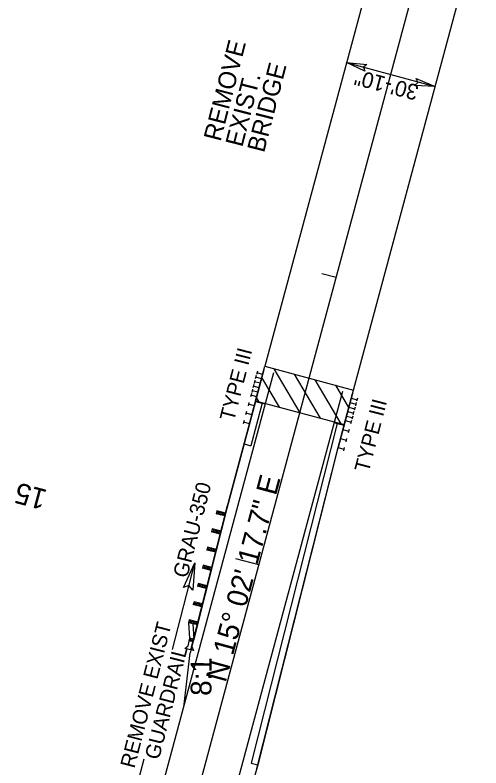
# Model space of a CAD drawing. Extents: x 2078889 to 2079501, y 925860 to 927219.
# Drawn here: x 2079214.2 to 2079370.7, y 926278.5 to 926531.6 of the extents above; entities that cross this region are included whole.
import ezdxf

# ---------------------------------------------------------------- set-up
doc = ezdxf.new("R2010")
doc.units = 0
for name, color, linetype in [('Exist Horizontal Alignment Direction Label', 7, 'Continuous'), ('Prop Approach Slab', 7, 'Continuous'), ('Prop Approach Slab Hatching', 7, 'Continuous'), ('Prop Conc Shoulder Berm Gutter', 7, 'Continuous'), ('Prop Dimension Text', 7, 'Continuous'), ('Prop DSN Text', 7, 'Continuous'), ('Prop EOT', 7, 'Continuous'), ('Prop Guardrail', 7, 'Continuous'), ('Prop Guardrail Anchor Unit CELL', 7, 'Continuous'), ('Prop Horizontal Alignment', 7, 'Continuous'), ('Prop Horizontal Alignment Tick Label', 7, 'Continuous'), ('Prop Horizontal Alignment Tick Large', 7, 'Continuous'), ('Prop Horizontal Alignment Tick Small', 7, 'Continuous'), ('Prop Paved Shoulder', 7, 'Continuous'), ('Prop Roadway Bridge', 7, 'Continuous'), ('Prop Structure Anchor Unit CELL', 7, 'Continuous'), ('Prop Terminator CELL', 7, 'Continuous'), ('Scratch_Level_1', 7, 'Continuous')]:
    doc.layers.add(name, color=color, linetype=linetype)

msp = doc.modelspace()

# ---------------------------------------------------------------- linework, layer by layer
at = {"layer": 'Prop Approach Slab'}
for p, q in [((2079294.99, 926401.93), (2079298.1, 926413.52)), ((2079324.75, 926393.94), (2079327.87, 926405.53)), ((2079294.99, 926401.93), (2079324.75, 926393.94))]:
    msp.add_line(p, q, dxfattribs=at)
at = {"layer": 'Prop Approach Slab Hatching'}
for p, q in [((2079309.93, 926397.92), (2079301.2, 926412.69)), ((2079316.83, 926396.07), (2079308.1, 926410.84)), ((2079303.02, 926399.78), (2079297.1, 926409.8)), ((2079323.73, 926394.21), (2079315, 926408.98)), ((2079326.3, 926399.7), (2079321.91, 926407.13)), ((2079296.12, 926401.63), (2079295.29, 926403.04))]:
    msp.add_line(p, q, dxfattribs=at)
at = {"layer": 'Prop Conc Shoulder Berm Gutter'}
for p, q in [((2079294.92, 926401.69), (2079291.1, 926387.45)), ((2079294.92, 926401.69), (2079297.18, 926401.09)), ((2079322.43, 926394.3), (2079324.69, 926393.7))]:
    msp.add_line(p, q, dxfattribs=at)
msp.add_lwpolyline([(2079324.69, 926393.69), (2079322.53, 926385.7), (2079295.72, 926279.55)], dxfattribs=at)
at = {"layer": 'Prop Dimension Text'}
for p, q in [((2079325.53, 926515.61), (2079355.26, 926507.5)), ((2079267.07, 926318.37), (2079274.56, 926347.49)), ((2079257.42, 926281.53), (2079253.89, 926267.81))]:
    msp.add_line(p, q, dxfattribs=at)
at = {"layer": 'Prop EOT'}
for p, q in [((2079217.85, 926101.67), (2079301.07, 926411.43)), ((2079241.03, 926095.44), (2079324.25, 926405.2))]:
    msp.add_line(p, q, dxfattribs=at)
at = {"layer": 'Prop Guardrail'}
for p, q in [((2079292.91, 926394.21), (2079284.97, 926364.5)), ((2079295.61, 926279.16), (2079322.68, 926386.21))]:
    msp.add_line(p, q, dxfattribs=at)
at = {"layer": 'Prop Guardrail Anchor Unit CELL'}
for p, q in [((2079285.55, 926366.68), (2079274.09, 926321.35)), ((2079282.02, 926364.95), (2079281.77, 926363.98)), ((2079284.93, 926364.21), (2079282.02, 926364.95)), ((2079283.23, 926363.61), (2079282.02, 926364.95)), ((2079281.77, 926363.98), (2079283.47, 926364.58)), ((2079284.68, 926363.24), (2079281.77, 926363.98)), ((2079283.47, 926364.58), (2079283.23, 926363.61)), ((2079283.23, 926363.61), (2079284.93, 926364.21)), ((2079284.68, 926363.24), (2079283.23, 926363.61)), ((2079283.47, 926364.58), (2079284.68, 926363.24)), ((2079284.93, 926364.21), (2079284.68, 926363.24)), ((2079280.42, 926358.85), (2079280.18, 926357.88)), ((2079280.18, 926357.88), (2079281.9, 926358.48)), ((2079283.14, 926357.13), (2079280.18, 926357.88)), ((2079283.38, 926358.1), (2079280.42, 926358.85)), ((2079281.66, 926357.51), (2079280.42, 926358.85)), ((2079281.9, 926358.48), (2079281.66, 926357.51)), ((2079283.38, 926358.1), (2079281.66, 926357.51)), ((2079281.9, 926358.48), (2079283.14, 926357.13)), ((2079278.88, 926352.74), (2079278.64, 926351.77)), ((2079278.64, 926351.77), (2079280.36, 926352.37)), ((2079281.84, 926351.99), (2079278.88, 926352.74)), ((2079280.11, 926351.4), (2079278.88, 926352.74)), ((2079280.36, 926352.37), (2079280.11, 926351.4)), ((2079281.84, 926351.99), (2079280.11, 926351.4)), ((2079280.36, 926352.37), (2079281.59, 926351.02)), ((2079281.59, 926351.02), (2079278.64, 926351.77)), ((2079277.35, 926346.63), (2079277.11, 926345.66)), ((2079277.11, 926345.66), (2079278.82, 926346.26)), ((2079280.05, 926344.91), (2079277.11, 926345.66)), ((2079280.29, 926345.88), (2079277.35, 926346.63)), ((2079278.58, 926345.29), (2079277.35, 926346.63)), ((2079278.82, 926346.26), (2079278.58, 926345.29)), ((2079280.29, 926345.88), (2079278.58, 926345.29)), ((2079278.82, 926346.26), (2079280.05, 926344.91)), ((2079280.29, 926345.88), (2079280.05, 926344.91)), ((2079275.71, 926340.54), (2079275.46, 926339.57)), ((2079275.46, 926339.57), (2079277.23, 926340.16)), ((2079278.5, 926338.8), (2079275.46, 926339.57)), ((2079278.75, 926339.77), (2079275.71, 926340.54)), ((2079276.98, 926339.19), (2079275.71, 926340.54)), ((2079277.23, 926340.16), (2079276.98, 926339.19)), ((2079278.75, 926339.77), (2079276.98, 926339.19)), ((2079277.23, 926340.16), (2079278.5, 926338.8)), ((2079274.3, 926334.4), (2079274.05, 926333.43)), ((2079277.2, 926333.67), (2079274.3, 926334.4)), ((2079275.5, 926333.06), (2079274.3, 926334.4)), ((2079274.05, 926333.43), (2079275.75, 926334.03)), ((2079276.96, 926332.7), (2079274.05, 926333.43)), ((2079275.75, 926334.03), (2079275.5, 926333.06)), ((2079277.2, 926333.67), (2079275.5, 926333.06)), ((2079275.75, 926334.03), (2079276.96, 926332.7)), ((2079272.69, 926328.31), (2079272.44, 926327.34)), ((2079272.44, 926327.34), (2079274.17, 926327.93)), ((2079275.42, 926326.59), (2079272.44, 926327.34)), ((2079272.44, 926327.34), (2079272.76, 926322.2)), ((2079275.66, 926327.56), (2079272.69, 926328.31)), ((2079273.93, 926326.96), (2079272.69, 926328.31)), ((2079274.17, 926327.93), (2079273.93, 926326.96)), ((2079275.66, 926327.56), (2079273.93, 926326.96)), ((2079273.93, 926326.96), (2079274.21, 926321.84)), ((2079274.17, 926327.93), (2079275.42, 926326.59)), ((2079272.36, 926319.62), (2079272.82, 926321.62)), ((2079272.76, 926322.2), (2079272.51, 926321.23)), ((2079272.51, 926321.23), (2079274.21, 926321.84)), ((2079272.76, 926322.2), (2079272.64, 926321.72)), ((2079274.21, 926321.84), (2079272.76, 926322.2)), ((2079273.97, 926320.87), (2079272.76, 926322.2)), ((2079272.82, 926321.62), (2079273.42, 926321.48)), ((2079271.25, 926318.67), (2079272.36, 926319.62)), ((2079273.97, 926320.87), (2079272.51, 926321.23)), ((2079273.42, 926321.48), (2079274.01, 926321.34)), ((2079274.01, 926321.34), (2079273.54, 926319.34)), ((2079273.54, 926319.34), (2079274.12, 926318)), ((2079274.12, 926318), (2079271.25, 926318.67))]:
    msp.add_line(p, q, dxfattribs=at)
at = {"layer": 'Prop Horizontal Alignment'}
msp.add_line((2079220.28, 926064.49), (2079368.62, 926616.59), dxfattribs=at)
at = {"layer": 'Prop Horizontal Alignment Tick Large'}
msp.add_line((2079296.12, 926346.75), (2079288.39, 926348.83), dxfattribs=at)
at = {"layer": 'Prop Horizontal Alignment Tick Small'}
msp.add_line((2079322.07, 926443.33), (2079317.24, 926444.62), dxfattribs=at)
at = {"layer": 'Prop Paved Shoulder'}
for p, q in [((2079297.18, 926401.09), (2079293.35, 926386.84)), ((2079298.22, 926400.81), (2079297.18, 926401.09)), ((2079322.44, 926394.3), (2079293.47, 926280.16)), ((2079321.39, 926394.58), (2079322.44, 926394.3)), ((2079291.1, 926387.45), (2079285.29, 926365.71)), ((2079291.1, 926387.45), (2079293.35, 926386.84)), ((2079285.29, 926365.71), (2079273, 926317.24)), ((2079270.86, 926299), (2079273, 926317.24)), ((2079293.47, 926280.16), (2079295.73, 926279.55))]:
    msp.add_line(p, q, dxfattribs=at)
msp.add_lwpolyline([(2079295.72, 926279.55), (2079294.45, 926274.85), (2079294.3, 926274.27), (2079293.79, 926272.27), (2079283.32, 926231.98)], dxfattribs=at)
at = {"layer": 'Prop Roadway Bridge'}
for p, q in [((2079340.91, 926572.87), (2079298.1, 926413.52)), ((2079327.87, 926405.53), (2079370.68, 926564.88)), ((2079298.1, 926413.52), (2079327.87, 926405.53))]:
    msp.add_line(p, q, dxfattribs=at)
at = {"layer": 'Prop Structure Anchor Unit CELL'}
for p, q in [((2079297.78, 926412.32), (2079292.91, 926394.21)), ((2079295.18, 926410.37), (2079294.89, 926409.26)), ((2079295.59, 926411.88), (2079295.29, 926410.77)), ((2079297.37, 926410.81), (2079295.44, 926411.33)), ((2079294.78, 926408.86), (2079294.48, 926407.75)), ((2079296.56, 926407.79), (2079294.63, 926408.31)), ((2079296.97, 926409.3), (2079295.04, 926409.82)), ((2079293.97, 926405.84), (2079293.67, 926404.74)), ((2079295.75, 926404.77), (2079293.82, 926405.29)), ((2079294.37, 926407.35), (2079294.08, 926406.25)), ((2079296.16, 926406.28), (2079294.22, 926406.8)), ((2079293.56, 926404.33), (2079293.26, 926403.23)), ((2079295.35, 926403.26), (2079293.41, 926403.78)), ((2079327.54, 926404.32), (2079322.68, 926386.21)), ((2079327.14, 926402.81), (2079329.07, 926402.29)), ((2079329.22, 926402.84), (2079328.92, 926401.74)), ((2079292.75, 926401.32), (2079292.45, 926400.21)), ((2079294.53, 926400.24), (2079292.6, 926400.76)), ((2079326.73, 926401.3), (2079328.66, 926400.78)), ((2079328.81, 926401.34), (2079328.51, 926400.23)), ((2079291.94, 926398.3), (2079291.64, 926397.19)), ((2079293.72, 926397.23), (2079291.79, 926397.74)), ((2079325.92, 926398.28), (2079327.85, 926397.76)), ((2079326.33, 926399.79), (2079328.26, 926399.27)), ((2079328, 926398.32), (2079327.7, 926397.21)), ((2079328.41, 926399.83), (2079328.11, 926398.72)), ((2079291.13, 926395.28), (2079290.83, 926394.17)), ((2079325.11, 926395.27), (2079327.04, 926394.75)), ((2079325.51, 926396.77), (2079327.45, 926396.26)), ((2079327.19, 926395.3), (2079326.89, 926394.19)), ((2079327.6, 926396.81), (2079327.3, 926395.7)), ((2079292.91, 926394.21), (2079290.98, 926394.73)), ((2079324.3, 926392.25), (2079326.23, 926391.73)), ((2079326.38, 926392.28), (2079326.08, 926391.18)), ((2079323.49, 926389.23), (2079325.42, 926388.71)), ((2079325.57, 926389.26), (2079325.27, 926388.16)), ((2079322.68, 926386.21), (2079324.61, 926385.69)), ((2079324.76, 926386.25), (2079324.46, 926385.14))]:
    msp.add_line(p, q, dxfattribs=at)
at = {"layer": 'Prop Terminator CELL'}
for points in [[(2079331.73, 926512.69), (2079325.53, 926515.61), (2079332.39, 926514.96), (2079331.24, 926514.03)], [(2079348.96, 926510.18), (2079355.26, 926507.5), (2079348.38, 926507.89), (2079349.5, 926508.86)], [(2079270.81, 926339.15), (2079274.56, 926347.49), (2079273.85, 926338.32), (2079272.59, 926339.83)]]:
    msp.add_lwpolyline(points, close=True, dxfattribs=at)
at = {"layer": 'Scratch_Level_1'}
for p, q in [((2079292.91, 926394.21), (2079297.78, 926412.32)), ((2079284.97, 926364.5), (2079292.91, 926394.21)), ((2079273.26, 926318.2), (2079285.55, 926366.68)), ((2079295.94, 926280.37), (2079295.73, 926279.55))]:
    msp.add_line(p, q, dxfattribs=at)
msp.add_lwpolyline([(2079295.4, 926278.34), (2079322.68, 926386.21), (2079327.54, 926404.32)], dxfattribs=at)

# ---------------------------------------------------------------- texts
at = {"layer": 'Exist Horizontal Alignment Direction Label'}
msp.add_text('N 15%%d 02\' 17.7" E', height=7, rotation=74.9617, dxfattribs=at).set_placement((2079284.92, 926306.98))
at = {"layer": 'Prop Dimension Text'}
msp.add_text('30\'-10"', height=5.25, rotation=165.5327, dxfattribs=at).set_placement((2079350.14, 926507.87))
at = {"layer": 'Prop DSN Text'}
for s, height, rotation, p in [('REMOVE ', 5.95, 75.5812, (2079283.21, 926488.82)), ('BRIDGE', 5.95, 75.5812, (2079297.82, 926485.06)), ('EXIST.', 5.95, 75.5812, (2079290.51, 926486.94)), ('REMOVE EXIST', 5, 75.5809, (2079254.29, 926278.19)), ('GUARDRAIL', 5, 75.5809, (2079262.51, 926281.04)), ('8:1', 7, 89.6276, (2079280.15, 926302.74))]:
    msp.add_text(s, height=height, rotation=rotation, dxfattribs=at).set_placement(p)
at = {"layer": 'Prop Guardrail Anchor Unit CELL'}
for s, p in [('TYPE III', (2079287.7, 926394.81)), ('TYPE III', (2079332.97, 926377.64)), ('GRAU-350', (2079272.01, 926342.12))]:
    msp.add_text(s, height=5, rotation=75.5809, dxfattribs=at).set_placement(p)
at = {"layer": 'Prop Horizontal Alignment Tick Label'}
msp.add_text('15', height=7, rotation=164.9617, dxfattribs=at).set_placement((2079225.32, 926371.85))

doc.saveas('drawing.dxf')
